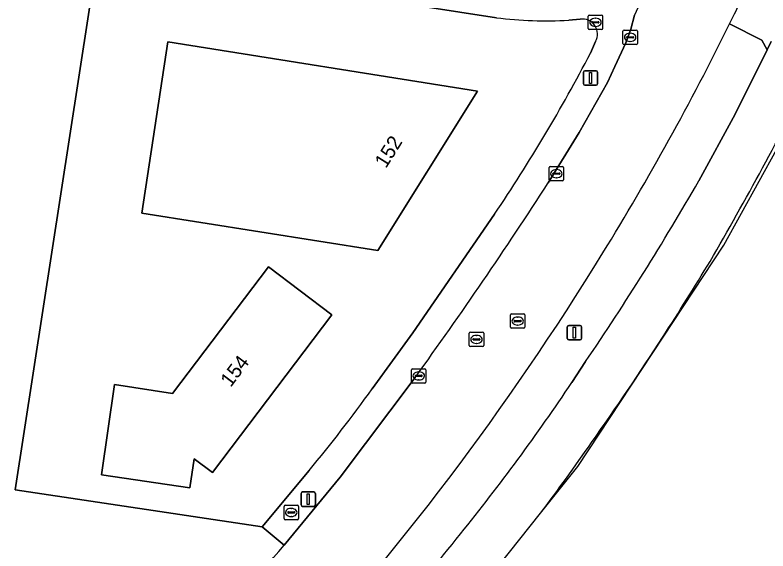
# Model space of a CAD drawing. Extents: x 154324 to 155744, y 382937 to 384188.
# Drawn here: x 155308.5 to 155360.7, y 383172.5 to 383209.7 of the extents above; entities that cross this region are included whole.
import ezdxf

# ---------------------------------------------------------------- set-up
doc = ezdxf.new("R2010")
doc.units = 0
for name, color, linetype in [('IMGEO_Berm_groen', 7, 'Continuous'), ('IMGEO_Brandkraan', 7, 'Continuous'), ('IMGEO_Erf', 7, 'Continuous'), ('IMGEO_Fietspad_gesloten', 7, 'Continuous'), ('IMGEO_Groenvoorziening', 7, 'Continuous'), ('IMGEO_Kolk', 7, 'Continuous'), ('IMGEO_Lichtmast', 7, 'Continuous'), ('IMGEO_Loofbos', 7, 'Continuous'), ('IMGEO_Pand', 7, 'Continuous'), ('IMGEO_Pand_nummerreeks', 7, 'Continuous'), ('IMGEO_Rijbaan_lokaal_gesloten', 7, 'Continuous'), ('IMGEO_Rioolput', 7, 'Continuous'), ('IMGEO_Voetpad_halfverhard', 7, 'Continuous'), ('IMGEO_Voetpad_open', 7, 'Continuous')]:
    doc.layers.add(name, color=color, linetype=linetype)

msp = doc.modelspace()

# ---------------------------------------------------------------- linework, layer by layer
at = {"layer": 'IMGEO_Berm_groen'}
for points in [[(155355.919, 383198.181), (155358.456, 383202.818), (155360.67, 383207.28), (155360.307, 383207.951), (155358.054, 383209.069)], [(155353.445, 383187.35), (155357.654, 383193.724), (155362.574, 383202.598), (155364.336, 383206.355), (155364.139, 383206.386), (155363.809, 383205.675)], [(155353.41, 383187.333), (155353.445, 383187.35)], [(155347.115, 383184.209), (155348.066, 383185.651)]]:
    msp.add_lwpolyline(points, dxfattribs=at)
for centre, radius, start, end in [((155188.155, 383292.744), 189.386, 328.28626, 333.7799), ((155133.956, 383322.194), 257.699, 329.81012, 333.11834), ((155183.585, 383297.463), 198.886, 325.79265, 330.05366), ((155184.314, 383294.508), 193.582, 317.22794, 328.4396), ((155183.327, 383297.202), 202.484, 327.13866, 328.89747), ((155227.765, 383263.937), 143.53, 321.04995, 326.2562), ((155105.125, 383362.184), 300.67, 318.33797, 321.18165)]:
    msp.add_arc(centre, radius, start, end, dxfattribs=at)
at = {"layer": 'IMGEO_Brandkraan'}
for p, q in [((155348.251, 383208.757), (155348.251, 383209.609)), ((155348.326, 383209.683), (155349.178, 383209.683)), ((155348.739, 383209.463), (155348.764, 383209.463)), ((155349.252, 383209.609), (155349.252, 383208.757)), ((155348.51, 383209.177), (155348.51, 383209.189)), ((155348.948, 383209.14), (155348.55, 383209.14)), ((155348.553, 383209.226), (155348.951, 383209.226)), ((155348.762, 383208.903), (155348.737, 383208.903)), ((155348.994, 383209.189), (155348.994, 383209.177)), ((155349.178, 383208.683), (155348.326, 383208.683)), ((155327.142, 383174.766), (155327.142, 383175.618)), ((155327.217, 383175.692), (155328.069, 383175.692)), ((155327.63, 383175.472), (155327.655, 383175.472)), ((155328.143, 383175.618), (155328.143, 383174.766)), ((155327.401, 383175.186), (155327.401, 383175.198)), ((155327.839, 383175.149), (155327.441, 383175.149)), ((155327.444, 383175.235), (155327.842, 383175.235)), ((155327.653, 383174.912), (155327.628, 383174.912)), ((155327.885, 383175.198), (155327.885, 383175.186)), ((155328.069, 383174.692), (155327.217, 383174.692))]:
    msp.add_line(p, q, dxfattribs=at)
for points in [[(155348.251, 383208.757), (155348.251, 383209.609)], [(155348.326, 383209.683), (155349.178, 383209.683)], [(155349.252, 383209.609), (155349.252, 383208.757)], [(155349.178, 383208.683), (155348.326, 383208.683)], [(155327.142, 383174.766), (155327.142, 383175.618)], [(155327.217, 383175.692), (155328.069, 383175.692)], [(155328.143, 383175.618), (155328.143, 383174.766)], [(155328.069, 383174.692), (155327.217, 383174.692)]]:
    msp.add_lwpolyline(points, dxfattribs=at)
for centre, radius, start, end in [((155348.328, 383209.607), 0.0765, 91.552, 178.448), ((155348.328, 383209.607), 0.0765, 91.552, 178.448), ((155349.176, 383209.607), 0.0765, 1.552, 88.448), ((155349.176, 383209.607), 0.0765, 1.552, 88.448), ((155348.55, 383209.186), 0.0403, 85.8775, 175.7526), ((155348.547, 383209.176), 0.0366, 178.938, 274.7102), ((155348.951, 383209.183), 0.043, 264.8664, 352.4533), ((155348.955, 383209.188), 0.0386, 1.7309, 96.639), ((155348.328, 383208.759), 0.0765, 181.552, 268.448), ((155348.328, 383208.759), 0.0765, 181.552, 268.448), ((155349.176, 383208.759), 0.0765, 271.552, 358.448), ((155349.176, 383208.759), 0.0765, 271.552, 358.448), ((155327.219, 383175.616), 0.0765, 91.552, 178.448), ((155327.219, 383175.616), 0.0765, 91.552, 178.448), ((155328.067, 383175.616), 0.0765, 1.552, 88.448), ((155328.067, 383175.616), 0.0765, 1.552, 88.448), ((155327.441, 383175.195), 0.0403, 85.8775, 175.7526), ((155327.438, 383175.185), 0.0366, 178.938, 274.7102), ((155327.842, 383175.192), 0.043, 264.8664, 352.4533), ((155327.846, 383175.197), 0.0386, 1.7309, 96.639), ((155327.219, 383174.768), 0.0765, 181.552, 268.448), ((155327.219, 383174.768), 0.0765, 181.552, 268.448), ((155328.067, 383174.768), 0.0765, 271.552, 358.448), ((155328.067, 383174.768), 0.0765, 271.552, 358.448)]:
    msp.add_arc(centre, radius, start, end, dxfattribs=at)
for centre, major_axis, ratio, start_param, end_param in [((155348.738, 383209.183), (-0.387, 0.002), 0.722429, 4.712389, 7.853982), ((155348.763, 383209.183), (-0.39, 0.002), 0.717154, 1.570796, 4.712389), ((155327.629, 383175.192), (-0.387, 0.002), 0.722429, 4.712389, 7.853982), ((155327.654, 383175.192), (-0.39, 0.002), 0.717154, 1.570796, 4.712389)]:
    msp.add_ellipse(centre, major_axis=major_axis, ratio=ratio, start_param=start_param, end_param=end_param, dxfattribs=at)
at = {"layer": 'IMGEO_Erf'}
for points in [[(155341.881, 383209.497), (155314.191, 383213.782), (155308.477, 383176.76), (155325.618, 383174.199), (155328.881, 383178.098)], [(155347.701, 383209.401), (155346.9, 383209.334)], [(155348.411, 383207.051), (155348.758, 383207.848)], [(155333.254, 383183.766), (155336.08, 383187.654), (155341.755, 383195.882)]]:
    msp.add_lwpolyline(points, dxfattribs=at)
for points in [[(155317.263, 383195.958), (155319.073, 383207.838), (155340.562, 383204.398), (155333.651, 383193.366)], [(155319.404, 383183.453), (155326.063, 383192.216), (155330.457, 383188.892), (155322.173, 383177.96), (155320.911, 383178.902), (155320.612, 383176.905), (155314.484, 383177.794), (155315.372, 383184.058)]]:
    msp.add_lwpolyline(points, close=True, dxfattribs=at)
for centre, radius, start, end in [((155345.282, 383236.86), 27.574, 262.9154, 273.3644), ((155347.844, 383208.362), 1.049, 330.6454, 97.8344), ((155245.072, 383261.066), 116.604, 326.01178, 332.40382), ((155249.814, 383243.621), 102.688, 320.35136, 324.34652)]:
    msp.add_arc(centre, radius, start, end, dxfattribs=at)
at = {"layer": 'IMGEO_Fietspad_gesloten'}
for points in [[(155360.954, 383207.852), (155360.67, 383207.28), (155358.456, 383202.818), (155355.919, 383198.181)], [(155348.066, 383185.651), (155347.115, 383184.209)], [(155339.204, 383167.929), (155344.942, 383175.14)]]:
    msp.add_lwpolyline(points, dxfattribs=at)
for centre, radius, start, end in [((155133.956, 383322.194), 257.699, 329.81012, 333.11834), ((155183.585, 383297.463), 198.886, 325.79265, 330.05366), ((155183.327, 383297.202), 202.484, 327.13866, 328.89747), ((155181.845, 383298.137), 204.235, 324.67432, 327.14402), ((155227.765, 383263.937), 143.53, 321.04995, 326.2562), ((155217.37, 383270.816), 159.463, 323.13085, 325.30266), ((155105.125, 383362.184), 300.67, 318.33797, 321.18165)]:
    msp.add_arc(centre, radius, start, end, dxfattribs=at)
at = {"layer": 'IMGEO_Groenvoorziening'}
msp.add_lwpolyline([(155327.148, 383172.921), (155325.618, 383174.199), (155308.477, 383176.76), (155314.191, 383213.782)], dxfattribs=at)
msp.add_arc((155190.327, 383288.705), 179.237, 314.01412, 319.76077, dxfattribs=at)
at = {"layer": 'IMGEO_Kolk'}
for p, q in [((155350.658, 383207.717), (155350.658, 383208.569)), ((155350.733, 383208.643), (155351.585, 383208.643)), ((155351.146, 383208.423), (155351.171, 383208.423)), ((155351.659, 383208.569), (155351.659, 383207.717)), ((155350.917, 383208.137), (155350.917, 383208.149)), ((155351.355, 383208.1), (155350.957, 383208.1)), ((155350.96, 383208.186), (155351.358, 383208.186)), ((155351.169, 383207.863), (155351.144, 383207.863)), ((155351.401, 383208.149), (155351.401, 383208.137)), ((155351.585, 383207.643), (155350.733, 383207.643)), ((155345.54, 383198.259), (155345.54, 383199.111)), ((155345.615, 383199.185), (155346.467, 383199.185)), ((155346.028, 383198.965), (155346.053, 383198.965)), ((155346.541, 383199.111), (155346.541, 383198.259)), ((155345.799, 383198.679), (155345.799, 383198.691)), ((155346.237, 383198.642), (155345.839, 383198.642)), ((155345.842, 383198.728), (155346.24, 383198.728)), ((155346.051, 383198.405), (155346.026, 383198.405)), ((155346.283, 383198.691), (155346.283, 383198.679)), ((155346.467, 383198.185), (155345.615, 383198.185)), ((155335.988, 383184.237), (155335.988, 383185.089)), ((155336.063, 383185.163), (155336.915, 383185.163)), ((155336.476, 383184.943), (155336.501, 383184.943)), ((155336.989, 383185.089), (155336.989, 383184.237)), ((155336.247, 383184.657), (155336.247, 383184.669)), ((155336.685, 383184.62), (155336.287, 383184.62)), ((155336.29, 383184.706), (155336.688, 383184.706)), ((155336.499, 383184.383), (155336.474, 383184.383)), ((155336.731, 383184.669), (155336.731, 383184.657)), ((155336.915, 383184.163), (155336.063, 383184.163))]:
    msp.add_line(p, q, dxfattribs=at)
for points in [[(155350.658, 383207.717), (155350.658, 383208.569)], [(155350.733, 383208.643), (155351.585, 383208.643)], [(155351.659, 383208.569), (155351.659, 383207.717)], [(155351.585, 383207.643), (155350.733, 383207.643)], [(155345.54, 383198.259), (155345.54, 383199.111)], [(155345.615, 383199.185), (155346.467, 383199.185)], [(155346.541, 383199.111), (155346.541, 383198.259)], [(155346.467, 383198.185), (155345.615, 383198.185)], [(155335.988, 383184.237), (155335.988, 383185.089)], [(155336.063, 383185.163), (155336.915, 383185.163)], [(155336.989, 383185.089), (155336.989, 383184.237)], [(155336.915, 383184.163), (155336.063, 383184.163)]]:
    msp.add_lwpolyline(points, dxfattribs=at)
for centre, radius, start, end in [((155350.735, 383208.567), 0.0765, 91.552, 178.448), ((155350.735, 383208.567), 0.0765, 91.552, 178.448), ((155351.583, 383208.567), 0.0765, 1.552, 88.448), ((155351.583, 383208.567), 0.0765, 1.552, 88.448), ((155350.957, 383208.146), 0.0403, 85.8775, 175.7526), ((155350.954, 383208.136), 0.0366, 178.938, 274.7102), ((155351.358, 383208.143), 0.043, 264.8664, 352.4533), ((155351.362, 383208.148), 0.0386, 1.7309, 96.639), ((155350.735, 383207.719), 0.0765, 181.552, 268.448), ((155350.735, 383207.719), 0.0765, 181.552, 268.448), ((155351.583, 383207.719), 0.0765, 271.552, 358.448), ((155351.583, 383207.719), 0.0765, 271.552, 358.448), ((155345.617, 383199.109), 0.0765, 91.552, 178.448), ((155345.617, 383199.109), 0.0765, 91.552, 178.448), ((155346.465, 383199.109), 0.0765, 1.552, 88.448), ((155346.465, 383199.109), 0.0765, 1.552, 88.448), ((155345.839, 383198.688), 0.0403, 85.8775, 175.7526), ((155345.836, 383198.678), 0.0366, 178.938, 274.7102), ((155346.24, 383198.685), 0.043, 264.8664, 352.4533), ((155346.244, 383198.69), 0.0386, 1.7309, 96.639), ((155345.617, 383198.261), 0.0765, 181.552, 268.448), ((155345.617, 383198.261), 0.0765, 181.552, 268.448), ((155346.465, 383198.261), 0.0765, 271.552, 358.448), ((155346.465, 383198.261), 0.0765, 271.552, 358.448), ((155336.065, 383185.087), 0.0765, 91.552, 178.448), ((155336.065, 383185.087), 0.0765, 91.552, 178.448), ((155336.913, 383185.087), 0.0765, 1.552, 88.448), ((155336.913, 383185.087), 0.0765, 1.552, 88.448), ((155336.287, 383184.666), 0.0403, 85.8775, 175.7526), ((155336.284, 383184.656), 0.0366, 178.938, 274.7102), ((155336.688, 383184.663), 0.043, 264.8664, 352.4533), ((155336.692, 383184.668), 0.0386, 1.7309, 96.639), ((155336.065, 383184.239), 0.0765, 181.552, 268.448), ((155336.065, 383184.239), 0.0765, 181.552, 268.448), ((155336.913, 383184.239), 0.0765, 271.552, 358.448), ((155336.913, 383184.239), 0.0765, 271.552, 358.448)]:
    msp.add_arc(centre, radius, start, end, dxfattribs=at)
for centre, major_axis, ratio, start_param, end_param in [((155351.145, 383208.143), (-0.387, 0.002), 0.722429, 4.712389, 7.853982), ((155351.17, 383208.143), (-0.39, 0.002), 0.717154, 1.570796, 4.712389), ((155346.027, 383198.685), (-0.387, 0.002), 0.722429, 4.712389, 7.853982), ((155346.052, 383198.685), (-0.39, 0.002), 0.717154, 1.570796, 4.712389), ((155336.475, 383184.663), (-0.387, 0.002), 0.722429, 4.712389, 7.853982), ((155336.5, 383184.663), (-0.39, 0.002), 0.717154, 1.570796, 4.712389)]:
    msp.add_ellipse(centre, major_axis=major_axis, ratio=ratio, start_param=start_param, end_param=end_param, dxfattribs=at)
at = {"layer": 'IMGEO_Lichtmast'}
for p, q in [((155347.912, 383204.918), (155347.912, 383205.718)), ((155347.912, 383205.718), (155347.912, 383204.918)), ((155348.012, 383205.818), (155348.802, 383205.818)), ((155348.802, 383205.818), (155348.012, 383205.818)), ((155348.902, 383205.718), (155348.902, 383204.918)), ((155348.902, 383204.918), (155348.902, 383205.718)), ((155348.802, 383204.818), (155348.012, 383204.818)), ((155348.012, 383204.818), (155348.802, 383204.818)), ((155346.796, 383187.26), (155346.796, 383188.06)), ((155346.796, 383188.06), (155346.796, 383187.26)), ((155346.896, 383188.16), (155347.686, 383188.16)), ((155347.686, 383188.16), (155346.896, 383188.16)), ((155347.786, 383188.06), (155347.786, 383187.26)), ((155347.786, 383187.26), (155347.786, 383188.06)), ((155347.686, 383187.16), (155346.896, 383187.16)), ((155346.896, 383187.16), (155347.686, 383187.16)), ((155328.326, 383175.715), (155328.326, 383176.515)), ((155328.326, 383176.515), (155328.326, 383175.715)), ((155328.426, 383176.615), (155329.216, 383176.615)), ((155329.216, 383176.615), (155328.426, 383176.615)), ((155329.316, 383176.515), (155329.316, 383175.715)), ((155329.316, 383175.715), (155329.316, 383176.515)), ((155329.216, 383175.615), (155328.426, 383175.615)), ((155328.426, 383175.615), (155329.216, 383175.615))]:
    msp.add_line(p, q, dxfattribs=at)
for points in [[(155348.332, 383205.693), (155348.482, 383205.693), (155348.482, 383204.943), (155348.332, 383204.943), (155348.332, 383205.693)], [(155347.216, 383188.035), (155347.366, 383188.035), (155347.366, 383187.285), (155347.216, 383187.285), (155347.216, 383188.035)], [(155328.746, 383176.49), (155328.896, 383176.49), (155328.896, 383175.74), (155328.746, 383175.74), (155328.746, 383176.49)]]:
    msp.add_lwpolyline(points, dxfattribs=at)
for centre, start, end in [((155348.012, 383205.718), 90, 180), ((155348.012, 383205.718), 90, 180), ((155348.802, 383205.718), 0, 90), ((155348.802, 383205.718), 360, 90), ((155348.012, 383204.918), 180, 270), ((155348.012, 383204.918), 180, 270), ((155348.802, 383204.918), 270, 0), ((155348.802, 383204.918), 270, 0), ((155346.896, 383188.06), 90, 180), ((155346.896, 383188.06), 90, 180), ((155347.686, 383188.06), 0, 90), ((155347.686, 383188.06), 360, 90), ((155346.896, 383187.26), 180, 270), ((155346.896, 383187.26), 180, 270), ((155347.686, 383187.26), 270, 0), ((155347.686, 383187.26), 270, 0), ((155328.426, 383176.515), 90, 180), ((155328.426, 383176.515), 90, 180), ((155329.216, 383176.515), 0, 90), ((155329.216, 383176.515), 360, 90), ((155328.426, 383175.715), 180, 270), ((155328.426, 383175.715), 180, 270), ((155329.216, 383175.715), 270, 0), ((155329.216, 383175.715), 270, 0)]:
    msp.add_arc(centre, 0.1, start, end, dxfattribs=at)
at = {"layer": 'IMGEO_Loofbos'}
msp.add_lwpolyline([(155344.942, 383175.14), (155347.525, 383178.386), (155353.445, 383187.35), (155353.41, 383187.333)], dxfattribs=at)
for centre, radius, start, end in [((155181.845, 383298.137), 204.235, 324.67432, 327.14402), ((155217.37, 383270.816), 159.463, 323.13085, 325.30266)]:
    msp.add_arc(centre, radius, start, end, dxfattribs=at)
at = {"layer": 'IMGEO_Pand'}
for points in [[(155340.562, 383204.398), (155319.073, 383207.838), (155317.263, 383195.958), (155333.651, 383193.366)], [(155320.911, 383178.902), (155322.173, 383177.96), (155330.457, 383188.892), (155326.063, 383192.216), (155319.404, 383183.453), (155315.372, 383184.058), (155314.484, 383177.794), (155320.612, 383176.905)]]:
    msp.add_lwpolyline(points, close=True, dxfattribs=at)
at = {"layer": 'IMGEO_Rijbaan_lokaal_gesloten'}
for points in [[(155358.678, 383225.57), (155351.45, 383209.687), (155351.21, 383208.71), (155350.852, 383207.764), (155350.097, 383206.13), (155349.584, 383205.02), (155347.619, 383201.535), (155345.477, 383198.049)], [(155336.24, 383184.543), (155331.031, 383177.647), (155327.148, 383172.921)]]:
    msp.add_lwpolyline(points, dxfattribs=at)
for centre, radius, start, end in [((155195.594, 383289.194), 181.144, 333.74751, 334.3964), ((155188.155, 383292.744), 189.386, 328.28626, 333.7799), ((155071.371, 383375.603), 326.588, 324.19561, 327.06652), ((155184.314, 383294.508), 193.582, 317.22794, 328.4396), ((155190.327, 383288.705), 179.237, 314.01412, 319.76077)]:
    msp.add_arc(centre, radius, start, end, dxfattribs=at)
at = {"layer": 'IMGEO_Rioolput'}
for p, q in [((155342.856, 383188.039), (155342.856, 383188.891)), ((155342.931, 383188.965), (155343.783, 383188.965)), ((155343.115, 383188.459), (155343.115, 383188.471)), ((155343.158, 383188.508), (155343.556, 383188.508)), ((155343.344, 383188.745), (155343.369, 383188.745)), ((155343.599, 383188.471), (155343.599, 383188.459)), ((155343.857, 383188.891), (155343.857, 383188.039)), ((155343.783, 383187.965), (155342.931, 383187.965)), ((155343.553, 383188.422), (155343.155, 383188.422)), ((155343.367, 383188.185), (155343.342, 383188.185)), ((155339.995, 383186.769), (155339.995, 383187.621)), ((155340.07, 383187.695), (155340.922, 383187.695)), ((155340.483, 383187.475), (155340.508, 383187.475)), ((155340.996, 383187.621), (155340.996, 383186.769)), ((155340.254, 383187.189), (155340.254, 383187.201)), ((155340.692, 383187.152), (155340.294, 383187.152)), ((155340.297, 383187.238), (155340.695, 383187.238)), ((155340.506, 383186.915), (155340.481, 383186.915)), ((155340.738, 383187.201), (155340.738, 383187.189)), ((155340.922, 383186.695), (155340.07, 383186.695))]:
    msp.add_line(p, q, dxfattribs=at)
for points in [[(155342.856, 383188.039), (155342.856, 383188.891)], [(155342.931, 383188.965), (155343.783, 383188.965)], [(155343.857, 383188.891), (155343.857, 383188.039)], [(155343.783, 383187.965), (155342.931, 383187.965)], [(155339.995, 383186.769), (155339.995, 383187.621)], [(155340.07, 383187.695), (155340.922, 383187.695)], [(155340.996, 383187.621), (155340.996, 383186.769)], [(155340.922, 383186.695), (155340.07, 383186.695)]]:
    msp.add_lwpolyline(points, dxfattribs=at)
for centre, radius, start, end in [((155342.933, 383188.889), 0.0765, 91.552, 178.448), ((155342.933, 383188.889), 0.0765, 91.552, 178.448), ((155343.155, 383188.468), 0.0403, 85.8775, 175.7526), ((155343.56, 383188.47), 0.0386, 1.7309, 96.639), ((155343.781, 383188.889), 0.0765, 1.552, 88.448), ((155343.781, 383188.889), 0.0765, 1.552, 88.448), ((155342.933, 383188.041), 0.0765, 181.552, 268.448), ((155342.933, 383188.041), 0.0765, 181.552, 268.448), ((155343.152, 383188.458), 0.0366, 178.938, 274.7102), ((155343.556, 383188.465), 0.043, 264.8664, 352.4533), ((155343.781, 383188.041), 0.0765, 271.552, 358.448), ((155343.781, 383188.041), 0.0765, 271.552, 358.448), ((155340.072, 383187.619), 0.0765, 91.552, 178.448), ((155340.072, 383187.619), 0.0765, 91.552, 178.448), ((155340.92, 383187.619), 0.0765, 1.552, 88.448), ((155340.92, 383187.619), 0.0765, 1.552, 88.448), ((155340.294, 383187.198), 0.0403, 85.8775, 175.7526), ((155340.291, 383187.188), 0.0366, 178.938, 274.7102), ((155340.695, 383187.195), 0.043, 264.8664, 352.4533), ((155340.699, 383187.2), 0.0386, 1.7309, 96.639), ((155340.072, 383186.771), 0.0765, 181.552, 268.448), ((155340.072, 383186.771), 0.0765, 181.552, 268.448), ((155340.92, 383186.771), 0.0765, 271.552, 358.448), ((155340.92, 383186.771), 0.0765, 271.552, 358.448)]:
    msp.add_arc(centre, radius, start, end, dxfattribs=at)
for centre, major_axis, ratio, start_param, end_param in [((155343.343, 383188.465), (-0.387, 0.002), 0.722429, 4.712389, 7.853982), ((155343.368, 383188.465), (-0.39, 0.002), 0.717154, 1.570796, 4.712389), ((155340.482, 383187.195), (-0.387, 0.002), 0.722429, 4.712389, 7.853982), ((155340.507, 383187.195), (-0.39, 0.002), 0.717154, 1.570796, 4.712389)]:
    msp.add_ellipse(centre, major_axis=major_axis, ratio=ratio, start_param=start_param, end_param=end_param, dxfattribs=at)
at = {"layer": 'IMGEO_Voetpad_halfverhard'}
msp.add_lwpolyline([(155358.054, 383209.069), (155360.307, 383207.951), (155360.67, 383207.28), (155360.954, 383207.852)], dxfattribs=at)
msp.add_arc((155195.594, 383289.194), 181.144, 333.74751, 334.3964, dxfattribs=at)
at = {"layer": 'IMGEO_Voetpad_open'}
for points in [[(155314.328, 383214.956), (155314.191, 383213.782), (155341.881, 383209.497)], [(155346.9, 383209.334), (155347.701, 383209.401)], [(155351.21, 383208.71), (155351.45, 383209.687)], [(155350.097, 383206.13), (155350.852, 383207.764), (155351.21, 383208.71)], [(155348.758, 383207.848), (155348.411, 383207.051)], [(155345.477, 383198.049), (155347.619, 383201.535), (155349.584, 383205.02), (155350.097, 383206.13)], [(155341.755, 383195.882), (155336.08, 383187.654), (155333.254, 383183.766)], [(155327.148, 383172.921), (155331.031, 383177.647), (155336.24, 383184.543)], [(155328.881, 383178.098), (155325.618, 383174.199), (155327.148, 383172.921)]]:
    msp.add_lwpolyline(points, dxfattribs=at)
for centre, radius, start, end in [((155345.282, 383236.86), 27.574, 262.9154, 273.3644), ((155347.844, 383208.362), 1.049, 330.6454, 97.8344), ((155245.072, 383261.066), 116.604, 326.01178, 332.40382), ((155071.371, 383375.603), 326.588, 324.19561, 327.06652), ((155249.814, 383243.621), 102.688, 320.35136, 324.34652)]:
    msp.add_arc(centre, radius, start, end, dxfattribs=at)

# ---------------------------------------------------------------- texts
at = {"layer": 'IMGEO_Pand_nummerreeks'}
for s, rotation, p in [('152', 58.0158, (155334.214, 383199.009)), ('154', 52.8564, (155323.438, 383183.825))]:
    msp.add_text(s, height=1, rotation=rotation, dxfattribs=at).set_placement(p)

doc.saveas('drawing.dxf')
